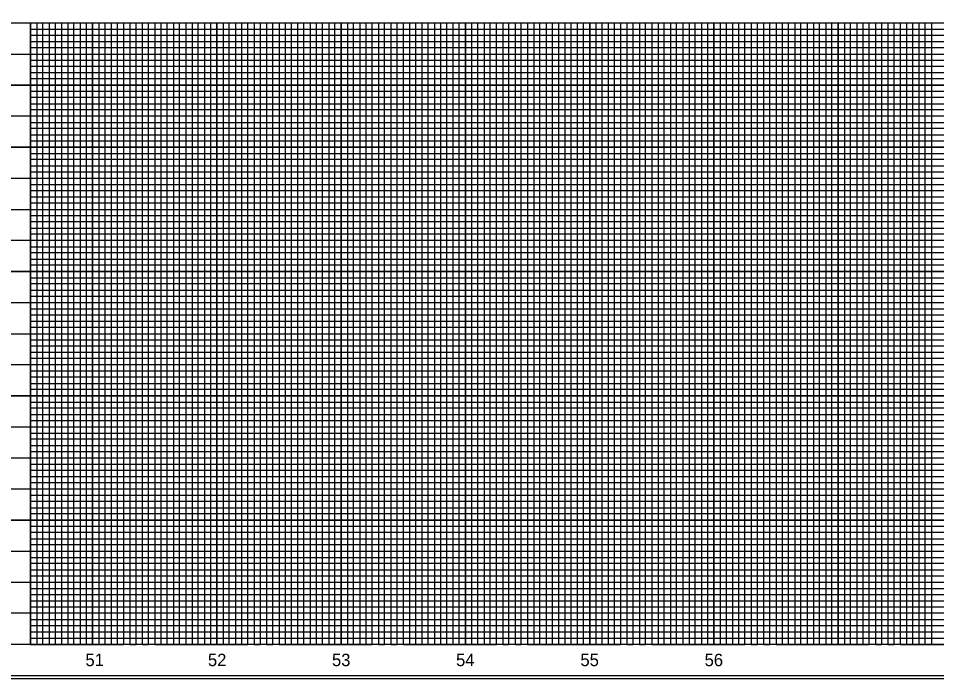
# Model space of a CAD drawing. Extents: x 1754992 to 1757273, y 732111 to 735411.
# Drawn here: x 1755388 to 1756127, y 733233 to 733764 of the extents above; entities that cross this region are included whole.
import ezdxf

# ---------------------------------------------------------------- set-up
doc = ezdxf.new("R2010")
doc.units = 0
for name, color, linetype in [('Scratch_Level_3', 7, 'Continuous'), ('Sheet DOT Grid CELL', 7, 'Continuous'), ('Sheet Plot Border Inside CELL', 7, 'Continuous'), ('Sheet Profile CELL', 7, 'Continuous'), ('Sheet Profile Grid Major CELL', 7, 'Continuous'), ('Sheet Profile Grid Middle CELL', 7, 'Continuous'), ('Sheet Profile Grid Minor CELL', 7, 'Continuous')]:
    doc.layers.add(name, color=color, linetype=linetype)

msp = doc.modelspace()

# ---------------------------------------------------------------- linework, layer by layer
at = {"layer": 'Scratch_Level_3'}
msp.add_lwpolyline([(1755397.67, 733760.78), (1756797.67, 733760.78), (1756797.67, 733260.78), (1755397.67, 733260.78)], close=True, dxfattribs=at)
at = {"layer": 'Sheet DOT Grid CELL'}
for p, q in [((1755347.67, 733760.78), (1756847.56, 733760.78)), ((1755397.67, 733760.78), (1755397.67, 733260.78)), ((1755447.67, 733760.78), (1755447.67, 733260.78)), ((1755497.67, 733760.78), (1755497.67, 733260.78)), ((1755547.67, 733760.78), (1755547.67, 733260.78)), ((1755597.67, 733760.78), (1755597.67, 733260.78)), ((1755647.67, 733760.78), (1755647.67, 733260.78)), ((1755697.67, 733760.78), (1755697.67, 733260.78)), ((1755747.67, 733760.78), (1755747.67, 733260.78)), ((1755797.67, 733760.78), (1755797.67, 733260.78)), ((1755847.67, 733760.78), (1755847.67, 733260.78)), ((1755897.67, 733760.78), (1755897.67, 733260.78)), ((1755947.67, 733760.78), (1755947.67, 733260.78)), ((1755997.67, 733760.78), (1755997.67, 733260.78)), ((1756047.67, 733760.78), (1756047.67, 733260.78)), ((1756097.67, 733760.78), (1756097.67, 733260.78)), ((1755347.67, 733710.78), (1756847.56, 733710.78)), ((1755347.67, 733660.78), (1756847.56, 733660.78)), ((1755347.67, 733610.78), (1756847.56, 733610.78)), ((1755347.67, 733560.78), (1756847.56, 733560.78)), ((1755347.67, 733510.78), (1756847.56, 733510.78)), ((1755347.67, 733460.78), (1756847.56, 733460.78)), ((1755347.67, 733410.78), (1756847.56, 733410.78)), ((1755347.67, 733360.78), (1756847.56, 733360.78)), ((1755347.67, 733310.78), (1756847.56, 733310.78))]:
    msp.add_line(p, q, dxfattribs=at)
at = {"layer": 'Sheet Plot Border Inside CELL'}
msp.add_lwpolyline([(1755193.67, 733233.23), (1756860.17, 733233.23), (1756860.17, 734288.33), (1755193.67, 734288.33)], close=True, dxfattribs=at)
at = {"layer": 'Sheet Profile CELL'}
for p, q in [((1755347.67, 733760.78), (1756847.67, 733760.78)), ((1756847.67, 733260.78), (1755347.67, 733260.78)), ((1755347.67, 733235.78), (1756847.67, 733235.78))]:
    msp.add_line(p, q, dxfattribs=at)
msp.add_lwpolyline([(1756847.67, 734285.78), (1755347.67, 734285.78), (1755347.67, 733235.78), (1756847.67, 733235.78)], close=True, dxfattribs=at)
at = {"layer": 'Sheet Profile Grid Major CELL'}
for p, q in [((1755847.67, 733760.78), (1755897.67, 733760.78)), ((1755947.67, 733760.78), (1755997.67, 733760.78)), ((1756047.67, 733760.78), (1756097.67, 733760.78))]:
    msp.add_line(p, q, dxfattribs=at)
for points in [[(1755397.67, 733760.78), (1755397.67, 733260.78), (1755447.67, 733260.78), (1755447.67, 733760.78), (1755497.67, 733760.78), (1755497.67, 733260.78), (1755547.67, 733260.78), (1755547.67, 733760.78), (1755597.67, 733760.78), (1755597.67, 733260.78), (1755647.67, 733260.78), (1755647.67, 733760.78), (1755697.67, 733760.78), (1755697.67, 733260.78), (1755747.67, 733260.78), (1755747.67, 733760.78), (1755797.67, 733760.78), (1755797.67, 733260.78), (1755847.67, 733260.78), (1755847.67, 733760.78), (1755897.67, 733760.78), (1755897.67, 733260.78), (1755947.67, 733260.78), (1755947.67, 733760.78), (1755997.67, 733760.78), (1755997.67, 733260.78), (1756047.67, 733260.78), (1756047.67, 733760.78), (1756097.67, 733760.78), (1756097.67, 733260.78), (1756147.67, 733260.78)], [(1756847.67, 733710.78), (1755347.67, 733710.78)], [(1756847.67, 733660.78), (1755347.67, 733660.78), (1755347.67, 733610.78), (1756847.67, 733610.78)], [(1756847.67, 733560.78), (1755347.67, 733560.78), (1755347.67, 733510.78), (1756847.67, 733510.78)], [(1756847.67, 733460.78), (1755347.67, 733460.78), (1755347.67, 733410.78), (1756847.67, 733410.78)], [(1756847.67, 733360.78), (1755347.67, 733360.78), (1755347.67, 733360.78), (1755347.67, 733310.78), (1756847.67, 733310.78)], [(1756847.67, 733260.78), (1755347.67, 733260.78)]]:
    msp.add_lwpolyline(points, dxfattribs=at)
at = {"layer": 'Sheet Profile Grid Middle CELL'}
for points in [[(1755372.67, 733760.78), (1755422.67, 733760.78), (1755422.67, 733260.78), (1755472.67, 733260.78), (1755472.67, 733760.78), (1755522.67, 733760.78), (1755522.67, 733260.78), (1755572.67, 733260.78), (1755572.67, 733760.78), (1755622.67, 733760.78), (1755622.67, 733260.78), (1755672.67, 733260.78), (1755672.67, 733760.78), (1755722.67, 733760.78), (1755722.67, 733260.78), (1755772.67, 733260.78), (1755772.67, 733760.78), (1755822.67, 733760.78), (1755822.67, 733260.78), (1755872.67, 733260.78), (1755872.67, 733760.78), (1755922.67, 733760.78), (1755922.67, 733260.78), (1755972.67, 733260.78), (1755972.67, 733260.78), (1755972.67, 733760.78), (1756022.67, 733760.78), (1756022.67, 733260.78), (1756072.67, 733260.78), (1756072.67, 733760.78), (1756122.67, 733760.78), (1756122.67, 733260.78), (1756172.67, 733260.78)], [(1755347.67, 733735.78), (1756847.67, 733735.78)], [(1756847.67, 733685.78), (1755347.67, 733685.78), (1755347.67, 733635.78), (1756847.67, 733635.78)], [(1756847.67, 733585.78), (1755347.67, 733585.78), (1755347.67, 733535.78), (1756847.67, 733535.78)], [(1756847.67, 733485.78), (1755347.67, 733485.78), (1755347.67, 733435.78), (1756847.67, 733435.78)], [(1756847.67, 733385.78), (1755347.67, 733385.78), (1755347.67, 733335.78), (1756847.67, 733335.78)], [(1756847.67, 733285.78), (1755347.67, 733285.78)]]:
    msp.add_lwpolyline(points, dxfattribs=at)
at = {"layer": 'Sheet Profile Grid Minor CELL'}
for p, q in [((1755397.67, 733755.78), (1756797.67, 733755.78)), ((1756797.67, 733750.78), (1755397.67, 733750.78)), ((1755397.67, 733745.78), (1756797.67, 733745.78)), ((1756797.67, 733740.78), (1755397.67, 733740.78)), ((1755397.67, 733730.78), (1756797.67, 733730.78)), ((1756797.67, 733725.78), (1755397.67, 733725.78)), ((1755397.67, 733720.78), (1756797.67, 733720.78)), ((1756797.67, 733715.78), (1755397.67, 733715.78)), ((1755397.67, 733705.78), (1756797.67, 733705.78)), ((1756797.67, 733700.78), (1755397.67, 733700.78)), ((1755397.67, 733695.78), (1756797.67, 733695.78)), ((1756797.67, 733690.78), (1755397.67, 733690.78)), ((1755397.67, 733680.78), (1756797.67, 733680.78)), ((1756797.67, 733675.78), (1755397.67, 733675.78)), ((1755397.67, 733670.78), (1756797.67, 733670.78)), ((1756797.67, 733665.78), (1755397.67, 733665.78)), ((1755397.67, 733655.78), (1756797.67, 733655.78)), ((1756797.67, 733650.78), (1755397.67, 733650.78)), ((1755397.67, 733645.78), (1756797.67, 733645.78)), ((1756797.67, 733640.78), (1755397.67, 733640.78)), ((1755397.67, 733630.78), (1756797.67, 733630.78)), ((1756797.67, 733625.78), (1755397.67, 733625.78)), ((1755397.67, 733620.78), (1756797.67, 733620.78)), ((1756797.67, 733615.78), (1755397.67, 733615.78)), ((1755397.67, 733605.78), (1756797.67, 733605.78)), ((1756797.67, 733600.78), (1755397.67, 733600.78)), ((1755397.67, 733595.78), (1756797.67, 733595.78)), ((1756797.67, 733590.78), (1755397.67, 733590.78)), ((1755397.67, 733580.78), (1756797.67, 733580.78)), ((1756797.67, 733575.78), (1755397.67, 733575.78)), ((1755397.67, 733570.78), (1756797.67, 733570.78)), ((1756797.67, 733565.78), (1755397.67, 733565.93)), ((1755397.67, 733555.78), (1756797.67, 733555.78)), ((1756797.67, 733550.78), (1755397.67, 733550.78)), ((1755397.67, 733545.78), (1756797.67, 733545.78)), ((1756797.67, 733540.78), (1755397.67, 733540.78)), ((1755397.67, 733530.78), (1756797.67, 733530.78)), ((1756797.67, 733525.78), (1755397.67, 733525.78)), ((1755397.67, 733520.78), (1756797.67, 733520.78)), ((1756797.67, 733515.78), (1755397.67, 733515.78)), ((1755397.67, 733505.78), (1756797.67, 733505.78)), ((1756797.67, 733500.78), (1755397.67, 733500.78)), ((1755397.67, 733495.78), (1756797.67, 733495.78)), ((1756797.67, 733490.78), (1755397.67, 733490.78)), ((1755397.67, 733480.78), (1756797.67, 733480.78)), ((1756797.67, 733475.78), (1755397.67, 733475.78)), ((1755397.67, 733470.78), (1756797.67, 733470.78)), ((1756797.67, 733465.78), (1755397.67, 733465.78)), ((1755397.67, 733455.78), (1756797.67, 733455.78)), ((1756797.67, 733450.78), (1755397.67, 733450.78)), ((1755397.67, 733445.78), (1756797.67, 733445.78)), ((1756797.67, 733440.78), (1755397.67, 733440.78)), ((1755397.67, 733430.78), (1756797.67, 733430.78)), ((1756797.67, 733425.78), (1755397.67, 733425.78)), ((1755397.67, 733420.78), (1756797.67, 733420.78)), ((1756797.67, 733415.78), (1755397.67, 733415.78)), ((1755397.67, 733405.78), (1756797.67, 733405.78)), ((1756797.67, 733400.78), (1755397.67, 733400.78)), ((1755397.67, 733395.78), (1756797.67, 733395.78)), ((1756797.67, 733390.78), (1755397.67, 733390.78)), ((1755397.67, 733380.78), (1756797.67, 733380.78)), ((1756797.67, 733375.78), (1755397.67, 733375.78)), ((1755397.67, 733370.78), (1756797.67, 733370.78)), ((1756797.67, 733365.78), (1755397.67, 733365.78)), ((1755397.67, 733355.78), (1756797.67, 733355.78)), ((1756797.67, 733350.78), (1755397.67, 733350.78)), ((1755397.67, 733345.78), (1756797.67, 733345.78)), ((1756797.67, 733340.78), (1755397.67, 733340.78)), ((1755397.67, 733330.78), (1756797.67, 733330.78)), ((1756797.67, 733325.78), (1755397.67, 733325.78)), ((1755397.67, 733320.78), (1756797.67, 733320.78)), ((1756797.67, 733315.78), (1755397.67, 733315.78)), ((1755397.67, 733305.78), (1756797.67, 733305.78)), ((1756797.67, 733300.78), (1755397.67, 733300.78)), ((1755397.67, 733295.78), (1756797.67, 733295.78)), ((1756797.67, 733290.78), (1755397.67, 733290.78)), ((1755397.67, 733280.78), (1756797.67, 733280.78)), ((1756797.67, 733275.78), (1755397.67, 733275.78)), ((1755397.67, 733270.78), (1756797.67, 733270.78)), ((1755397.67, 733265.78), (1756797.67, 733265.78))]:
    msp.add_line(p, q, dxfattribs=at)
for points in [[(1755397.67, 733760.78), (1755402.67, 733760.78), (1755402.67, 733260.78), (1755407.67, 733260.78), (1755407.67, 733760.78), (1755412.67, 733760.78), (1755412.67, 733260.78), (1755417.67, 733260.78), (1755417.67, 733760.78), (1755427.67, 733760.78), (1755427.67, 733260.78), (1755432.67, 733260.78), (1755432.67, 733760.78), (1755437.67, 733760.78), (1755437.67, 733260.78), (1755442.67, 733260.78), (1755452.67, 733260.78), (1755457.67, 733260.78), (1755457.67, 733760.78), (1755462.67, 733760.78), (1755462.67, 733260.78), (1755467.67, 733260.78), (1755467.67, 733760.78), (1755477.67, 733760.78), (1755477.67, 733260.78), (1755482.67, 733260.78), (1755482.67, 733760.78), (1755487.67, 733760.78), (1755487.67, 733260.78), (1755492.67, 733260.78), (1755492.67, 733760.78), (1755502.67, 733760.78), (1755502.67, 733260.78), (1755507.67, 733260.78), (1755507.67, 733760.78), (1755512.67, 733760.78), (1755512.67, 733260.78), (1755517.67, 733260.78), (1755517.67, 733760.78), (1755527.67, 733760.78), (1755527.67, 733260.78), (1755532.67, 733260.78), (1755532.67, 733760.78), (1755537.67, 733760.78), (1755537.67, 733260.78), (1755542.67, 733260.78), (1755542.67, 733760.78), (1755552.67, 733760.78), (1755552.67, 733260.78), (1755557.67, 733260.78), (1755557.67, 733760.78), (1755562.67, 733760.78), (1755562.67, 733260.78), (1755567.67, 733260.78), (1755567.67, 733760.78), (1755577.67, 733760.78), (1755577.67, 733260.78), (1755582.67, 733260.78), (1755582.67, 733760.78), (1755587.67, 733760.78), (1755587.67, 733260.78), (1755592.67, 733260.78), (1755592.67, 733760.78), (1755602.67, 733760.78), (1755602.67, 733260.78), (1755607.67, 733260.78), (1755607.67, 733760.78), (1755612.67, 733760.78), (1755612.67, 733260.78)], [(1755442.67, 733260.78), (1755442.67, 733760.78), (1755452.67, 733760.78), (1755452.67, 733260.78)], [(1755612.67, 733260.78), (1755617.67, 733260.78), (1755617.67, 733760.78), (1755627.67, 733760.78), (1755627.67, 733260.78), (1755632.67, 733260.78), (1755632.67, 733760.78), (1755637.67, 733760.78), (1755637.67, 733260.78), (1755642.67, 733260.78), (1755642.67, 733760.78), (1755652.67, 733760.78), (1755652.67, 733260.78), (1755657.67, 733260.78), (1755657.67, 733760.78), (1755662.67, 733760.78), (1755662.67, 733260.78), (1755667.67, 733260.78), (1755667.67, 733760.78), (1755677.67, 733760.78), (1755677.67, 733260.78), (1755682.67, 733260.78), (1755682.67, 733760.78), (1755687.67, 733760.78), (1755687.67, 733260.78), (1755692.67, 733260.78), (1755692.67, 733760.78), (1755702.67, 733760.78), (1755702.67, 733260.78), (1755707.67, 733260.78), (1755707.67, 733760.78), (1755712.67, 733760.78), (1755712.67, 733260.78), (1755717.67, 733260.78), (1755717.67, 733760.78), (1755727.67, 733760.78), (1755727.67, 733260.78), (1755732.67, 733260.78), (1755732.67, 733760.78), (1755737.67, 733760.78), (1755737.67, 733260.78), (1755742.67, 733260.78), (1755742.67, 733760.78), (1755752.67, 733760.78), (1755752.67, 733260.78), (1755757.67, 733260.78), (1755757.67, 733760.78), (1755762.67, 733760.78), (1755762.67, 733260.78), (1755767.67, 733260.78), (1755767.67, 733760.78), (1755777.67, 733760.78), (1755777.67, 733260.78), (1755782.67, 733260.78), (1755782.67, 733760.78), (1755787.67, 733760.78), (1755787.67, 733260.78), (1755792.67, 733260.78), (1755792.67, 733760.78), (1755802.67, 733760.78), (1755802.67, 733260.78), (1755807.67, 733260.78), (1755807.67, 733760.78), (1755812.67, 733760.78), (1755812.67, 733260.78), (1755817.67, 733260.78), (1755817.67, 733760.78), (1755827.67, 733760.78), (1755827.67, 733260.78), (1755832.67, 733260.78), (1755832.67, 733760.78), (1755837.67, 733760.78), (1755837.67, 733260.78), (1755842.67, 733260.78), (1755842.67, 733760.78), (1755852.67, 733760.78), (1755852.67, 733260.78), (1755857.67, 733260.78), (1755857.67, 733760.78), (1755862.67, 733760.78), (1755862.67, 733260.78), (1755867.67, 733260.78), (1755867.67, 733760.78), (1755877.67, 733760.78), (1755877.67, 733260.78), (1755882.67, 733260.78), (1755882.67, 733760.78), (1755887.67, 733760.78), (1755887.67, 733260.78), (1755892.67, 733260.78), (1755892.67, 733760.78), (1755902.67, 733760.78), (1755902.67, 733260.78), (1755907.67, 733260.78), (1755907.67, 733760.78), (1755912.67, 733760.78), (1755912.67, 733260.78), (1755917.67, 733260.78), (1755917.67, 733760.78), (1755927.67, 733760.78)], [(1755927.67, 733760.78), (1755927.67, 733260.78), (1755932.67, 733260.78), (1755932.67, 733760.78), (1755937.67, 733760.78), (1755937.67, 733260.78), (1755942.67, 733260.78), (1755942.67, 733760.78), (1755952.67, 733760.78), (1755952.67, 733260.78), (1755957.67, 733260.78), (1755957.67, 733760.78), (1755962.67, 733760.78), (1755962.67, 733260.78), (1755967.67, 733260.78), (1755967.67, 733760.78), (1755977.67, 733760.78), (1755977.67, 733260.78), (1755982.67, 733260.78), (1755982.67, 733760.78), (1755987.67, 733760.78), (1755987.67, 733260.78), (1755992.67, 733260.78), (1755992.67, 733760.78), (1756002.67, 733760.78), (1756002.67, 733260.78), (1756007.67, 733260.78), (1756007.67, 733760.78), (1756012.67, 733760.78), (1756012.67, 733260.78), (1756017.67, 733260.78), (1756017.67, 733760.78), (1756027.67, 733760.78), (1756027.67, 733260.78), (1756032.67, 733260.78), (1756032.67, 733760.78), (1756037.67, 733760.78), (1756037.67, 733260.78), (1756042.67, 733260.78), (1756042.67, 733760.78), (1756052.67, 733760.78), (1756052.67, 733260.78), (1756052.67, 733260.78), (1756057.67, 733260.78), (1756057.67, 733760.78), (1756062.67, 733760.78), (1756062.67, 733260.78), (1756067.67, 733260.78), (1756067.67, 733760.78), (1756077.67, 733760.78), (1756077.67, 733260.78), (1756082.67, 733260.78), (1756082.67, 733760.78), (1756087.67, 733760.78), (1756087.67, 733260.78), (1756092.67, 733260.78), (1756092.67, 733760.78), (1756102.67, 733760.78), (1756102.67, 733260.78), (1756107.67, 733260.78), (1756107.67, 733760.78), (1756112.67, 733760.78), (1756112.67, 733260.78), (1756117.67, 733260.78), (1756117.67, 733760.78), (1756127.67, 733760.78)]]:
    msp.add_lwpolyline(points, dxfattribs=at)

# ---------------------------------------------------------------- texts
at = {"layer": 'Scratch_Level_3'}
for s, p in [('51', (1755441.89, 733243.28)), ('52', (1755540.44, 733243.28)), ('53', (1755640.28, 733243.28)), ('54', (1755740.12, 733243.28)), ('55', (1755840.21, 733243.28)), ('56', (1755940.15, 733243.28))]:
    msp.add_text(s, height=10, dxfattribs=at).set_placement(p)

doc.saveas('drawing.dxf')
